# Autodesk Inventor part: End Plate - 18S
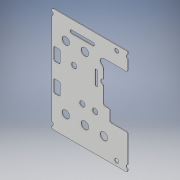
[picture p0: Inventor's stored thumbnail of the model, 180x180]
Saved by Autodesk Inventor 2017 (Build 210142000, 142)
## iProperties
Created: 2021-03
Part Number: End Plate - 18S
Material: Generic
Document SubType Name: Modeling
Designer: Win240
Density: 1 g/cm^3
Appearance: Default
Author: Win240
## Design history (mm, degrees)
sketch "Sketch1"
  geometry: L1 (0, 0)-(119, 0); L2 (119, 0)-(119, -28); L3 (119, -165)-(0, -165); L4 (0, -165)-(0, 0); L5 (-1, -7.5)-(120, -7.5); L6 (120, -7.5)-(120, -157.5); L7 (120, -157.5)-(-1, -157.5); L8 (-1, -157.5)-(-1, -7.5); L9 (-1, -7.5)-(0, -4.408); L10 (120, -7.5)-(119, -4.408); L11 (59.5, -7.5)-(59.5, 0); L12 (59.5, -157.5)-(59.5, -165); L13 (22, -34)-(52, -34); L14 (52, -34)-(82, -34); L15 (82, -34)-(82, -134); L16 (82, -134)-(52, -134); L17 (52, -134)-(22, -134); L18 (22, -134)-(22, -34); L19 (68, -48.5)-(72, -48.5); L20 (72, -48.5)-(72, -72.5); L21 (72, -72.5)-(68, -72.5); L22 (68, -72.5)-(68, -48.5); L23 (82, -28)-(119, -28); L24 (81, -43.747)-(81, -92.5); L25 (48, -107)-(68, -107); L26 (35, -61)-(81, -61); L27 (81, -92.5)-(91, -92.5); L28 (91, -92.5)-(91, -110.5); L29 (91, -110.5)-(119, -110.5); L30 (119, -28)-(119, -110.5); L31 (119, -110.5)-(119, -165); L32 (102, -7.5)-(102, -157.5); C1 r 6 at (22, -34); C2 r 6 at (52, -34); C3 r 6 at (82, -134); C4 r 6 at (52, -134); C5 r 6 at (22, -134); C6 r 4.25 at (68, -107); C7 r 4.25 at (35, -61); C8 r 3.25 at (102, -7.5); C9 r 4.25 at (48, -107); C10 r 3.25 at (102, -157.5); A1 r 3.25 centre (-1, -7.5) between (0, -10.592) and (0, -4.408); A2 r 3.25 centre (120, -7.5) between (119, -4.408) and (119, -10.592); A3 r 3.25 centre (120, -157.5) between (119, -154.408) and (119, -160.592); A4 r 3.25 centre (-1, -157.5) between (0, -160.592) and (0, -154.408); A5 r 6 centre (82, -34) between (82, -28) and (78.5, -38.873); A6 r 4.25 centre (81, -61) between (81, -56.75) and (81, -65.25); A7 r 6 centre (75, -43.747) between (81, -43.747) and (78.5, -38.873); A8 r 6 centre (82, -34) between (82, -40) and (82, -28); A9 r 6 centre (82, -34) between (78.5, -38.873) and (82, -40); A10 r 4.25 centre (81, -61) between (82, -56.869) and (81, -56.75); A11 r 4.25 centre (81, -61) between (82, -65.131) and (82, -56.869); A12 r 4.25 centre (81, -61) between (81, -65.25) and (82, -65.131)
  constraints: 64 end point, 24 point on circle, 22 centre point, 20 point on line, 14 equal radius, 13 horizontal, 8 vertical, 6 parallel, 4 midpoint, 4 perpendicular, 4 tangent, 3 equal length
  dimensions: "d0" = 119 distance of L3.start L3.end; "d1" = 165 distance of L1.end L3.start; "d2" = 150 distance of L5.end L6.end; "d3" = 121 distance of L6.end L7.end; "d4" = 3.25 radius of A1; "d5" = 12 diameter of C1; "d6" = 30 distance of L13.start L13.end; "d7" = 100 distance of L17.end L13.start; "d8" = 26.5 distance between parallel lines of L5 L13; "d9" = 23 distance between parallel lines of L18 L8; "d10" = 8.5 diameter of C7; "d11" = 36 distance from line of L26.start L8; "d12" = 69 distance from line of L25.end L8; "d13" = 53.5 distance from line of L26.start L5; "d14" = 99.5 distance from line of L5 L25.end; "d15" = 103 distance of L32.start L5.start; "d16" = 65 distance between parallel lines of L21 L5; "d17" = 41 distance between parallel lines of L19 L5; "d18" = 69 distance between parallel lines of L22 L8; "d19" = 73 distance between parallel lines of L20 L8; "d20" = 82 distance between parallel lines of L8 L24; "d21" = 82 distance from line of L8 L26.end; "d22" = 49 distance from line of L25.start L8; "d23" = 85 distance between parallel lines of L5 L27; "d24" = 92 distance between parallel lines of L8 L28; "d25" = 103 distance between parallel lines of L5 L29
extrude "Mechanical Holes" new body sketch "Sketch1" distance "d26" = 1; taper "d27" = 0 deg
sketch "Sketch2"
  geometry: L1 (0, -10.592)-(0, -154.408) reference; L2 (119, 0)-(0, 0) reference; L3 (0, -165)-(119, -165) reference; L4 (67, -14.5)-(29, -14.5); L5 (29, -14.5)-(29, -19.5); L6 (29, -19.5)-(67, -19.5); L7 (67, -19.5)-(67, -14.5); L8 (3, -50.5)-(13, -50.5); L9 (13, -50.5)-(13, -70.5); L10 (13, -70.5)-(3, -70.5); L11 (3, -70.5)-(3, -50.5); L12 (13, -94.5)-(3, -94.5); L13 (3, -94.5)-(3, -114.5); L14 (3, -114.5)-(13, -114.5); L15 (13, -114.5)-(13, -94.5); A1 r 3.25 centre (-1, -7.5) between (0, -10.592) and (0, -4.408) reference
  constraints: 24 end point, 6 parallel, 3 collinear, 3 horizontal, 3 perpendicular
  dimensions: "d28" = 4 distance from line of L11 A1.centre; "d29" = 10 distance of L8.start L8.end; "d30" = 63 distance from line of L10 A1.centre; "d31" = 87 distance from line of L12 A1.centre; "d32" = 20 distance of L8.end L9.end; "d33" = 7 distance from line of A1.centre L4; "d34" = 12 distance from line of A1.centre L6; "d35" = 30 distance from line of L5 A1.centre; "d36" = 68 distance from line of A1.centre L7
extrude "Air Holes" cut sketch "Sketch2" stored distance "d37" = 1; taper "d38" = 0 deg
fillet "Fillet1" dims "d39" = 2
body "Solid1"
